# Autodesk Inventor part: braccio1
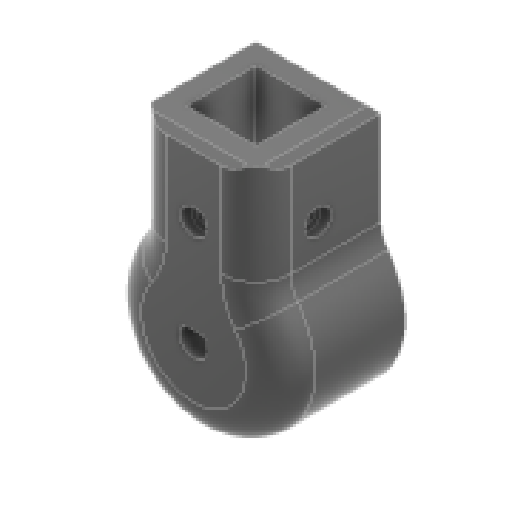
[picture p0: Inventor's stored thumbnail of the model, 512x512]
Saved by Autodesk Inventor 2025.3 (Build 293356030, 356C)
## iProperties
Created: 2026-03
Part Number: braccio1
Material: Plastica ABS
Document SubType Name: Modeling
Designer: R5800u
Density: 1.06 g/cm^3
Appearance: Liscia - Nero
Author: R5800u
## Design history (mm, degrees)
sketch "Schizzo1"
  geometry: L1 (-2.646, 3)-(2.646, 3); C1 r 25 at (0, 0); A1 r 4 centre (0, 0) between (-2.646, 3) and (2.646, 3); 1 further point
  constraints: 2 centre point, 2 coincident, 2 end point, 2 point on circle, 1 horizontal
  dimensions: "d0" = 50 diameter of C1; "d1" = 8 diameter of A1; "d2" = 3 distance from line of point (0, 0) L1
extrude "Estrusione1" new body sketch "Schizzo1" stored distance "d3" = 36; taper "d4" = 0 deg
node "Piano di lavoro1"
sketch "Schizzo2"
  geometry: L1 (18, 18)-(-18, 18); L2 (-18, 18)-(-18, -18); L3 (-18, -18)-(18, -18); L4 (18, -18)-(18, 18); L5 (18, 18)-(-18, -18); L6 (-18, 18)-(18, -18); L7 (10, 10)-(-10, 10); L8 (-10, 10)-(-10, -10); L9 (-10, -10)-(10, -10); L10 (10, -10)-(10, 10); L11 (10, 10)-(-10, -10); L12 (-10, 10)-(10, -10); 1 further point
  constraints: 24 end point, 4 midpoint, 4 parallel, 2 horizontal, 2 perpendicular
  dimensions: "d6" = 36 distance of L3.end L2.end; "d7" = 36 distance of L2.end L1.end; "d8" = 20 distance of L9.end L8.end; "d9" = 20 distance of L8.end L7.end
extrude "Estrusione2" join sketch "Schizzo2" stored distance "d10" = 10; taper "d11" = 0 deg
sketch "Schizzo3"
  geometry: L1 (-10, 50)-(10, 50) reference; L2 (0, 50)-(0, 30); 1 further point
  constraints: 2 end point, 1 midpoint, 1 vertical
  dimensions: "d16" = 20 distance of L2.start L2.end
hole "Foro1" sketch "Schizzo3" at (0, 30) diameter "d17" = 4.3; stored, may be unused: countersink angle "d21" = 90 deg, drill point angle "d23" = 118 deg; dims "d18" = 6, "d19" = 7.5, "d20" = 3, "d22" = 8
pattern_circular "Serie circolare1" dims angle "d25" = 360 deg
chamfer "Smusso2" distance "d27" = 2; stored, may be unused: second distance "d28" = 2, angle "d29" = 45 deg
fillet "Raccordo2" dims "d30" = 10
fillet "Raccordo3" dims "d31" = 10
node "Solido1"
